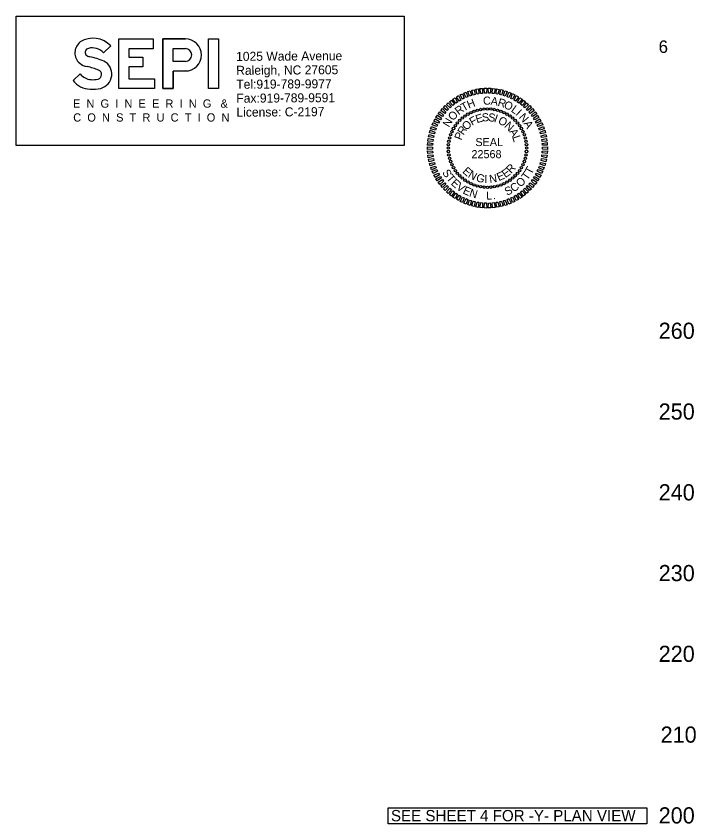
# Model space of a CAD drawing. Extents: x 2319808 to 2329388, y 152694 to 160631.
# Drawn here: x 2320852 to 2321272, y 152694 to 153194 of the extents above; entities that cross this region are included whole.
import ezdxf

# ---------------------------------------------------------------- set-up
doc = ezdxf.new("R2010")
doc.units = 0
for name, color, linetype in [('Exist Vertical Profile Vertical Axis Label', 7, 'Continuous'), ('Old_Level_2', 7, 'Continuous'), ('Old_Level_58', 7, 'Continuous'), ('Old_Level_61', 7, 'Continuous'), ('Prop Grid Mask', 7, 'Continuous'), ('Prop PFL Text', 7, 'Continuous'), ('Sheet Data Field CELL', 7, 'Continuous'), ('Sheet PE Seal Cell', 7, 'Continuous')]:
    doc.layers.add(name, color=color, linetype=linetype)

msp = doc.modelspace()

# ---------------------------------------------------------------- linework, layer by layer
at = {"layer": 'Old_Level_58'}
msp.add_lwpolyline([(2320852, 153193.7), (2321092.06, 153193.7), (2321092.06, 153113.67), (2320852, 153113.67)], close=True, dxfattribs=at)
at = {"layer": 'Old_Level_61'}
for p, q in [((2320910.53, 153175.25), (2320906.11, 153170.94)), ((2320915.52, 153179.56), (2320936.8, 153179.57)), ((2320915.52, 153148.91), (2320915.52, 153179.56)), ((2320936.8, 153179.57), (2320936.8, 153173.57)), ((2320956.69, 153179.57), (2320942.84, 153179.57)), ((2320970.97, 153179.57), (2320977.11, 153179.57)), ((2320970.97, 153148.91), (2320970.97, 153179.57)), ((2320977.11, 153179.57), (2320977.11, 153148.91)), ((2320936.8, 153173.57), (2320921.63, 153173.57)), ((2320921.63, 153173.57), (2320921.63, 153168.28)), ((2320921.63, 153168.28), (2320930.4, 153168.28)), ((2320930.4, 153168.28), (2320930.4, 153162.32)), ((2320956.69, 153165.72), (2320949.09, 153165.72)), ((2320930.4, 153162.32), (2320921.63, 153162.32)), ((2320921.63, 153162.32), (2320921.63, 153154.88)), ((2320887.18, 153153.96), (2320891.63, 153157.93)), ((2320921.63, 153154.88), (2320937.5, 153154.88)), ((2320937.5, 153154.88), (2320937.5, 153148.91)), ((2320937.5, 153148.91), (2320915.52, 153148.91)), ((2320977.11, 153148.91), (2320970.97, 153148.91))]:
    msp.add_line(p, q, dxfattribs=at)
for points in [[(2320942.84, 153179.57), (2320956.69, 153179.57)], [(2320956.69, 153159.75), (2320949.1, 153159.74), (2320949.1, 153148.91), (2320942.84, 153148.91), (2320942.84, 153179.57)], [(2320942.84, 153179.57), (2320942.84, 153148.91), (2320949.1, 153148.91), (2320949.1, 153159.74), (2320956.69, 153159.75)], [(2320949.09, 153165.72), (2320949.09, 153173.62), (2320956.69, 153173.62)], [(2320949.09, 153165.72), (2320949.09, 153173.62), (2320956.69, 153173.62)], [(2320956.69, 153165.72), (2320949.09, 153165.72)]]:
    msp.add_lwpolyline(points, dxfattribs=at)
for centre, radius, start, end in [((2320899.64, 153165.4), 14.68, 42.1327, 122.9781), ((2320896.85, 153170.99), 8.51, 127.737, 229.6653), ((2320956.69, 153169.66), 9.91, 270.0085, 90.0085), ((2320956.69, 153169.66), 9.91, 270.0085, 90.0085), ((2320897.26, 153171.29), 2.54, 103.531, 215.5148), ((2320899.12, 153164.73), 9.35, 41.6206, 105.1978), ((2320956.69, 153169.67), 3.95, 270.0085, 90.0085), ((2320956.69, 153169.67), 3.95, 270.0085, 90.0085), ((2320898.64, 153173.24), 4.86, 224.8336, 256.8488), ((2320889.71, 153126.77), 42.47, 67.2047, 79.3861), ((2320902.13, 153157.8), 9.06, 283.8987, 63.5916), ((2320898.66, 153174.58), 12.45, 234.0275, 257.3508), ((2320888.8, 153125.52), 37.6, 67.7856, 79.0604), ((2320901.85, 153157.62), 2.95, 286.1134, 66.6483), ((2320899.02, 153163.95), 9.54, 219.2143, 265.7729), ((2320897.99, 153161.91), 13.42, 216.3695, 269.0232), ((2320899.59, 153166.23), 11.85, 263.8472, 285.0485), ((2320899.48, 153168.72), 20.3, 265.1339, 283.7745)]:
    msp.add_arc(centre, radius, start, end, dxfattribs=at)
at = {"layer": 'Prop Grid Mask'}
msp.add_lwpolyline([(2321082.06, 152703.7), (2321242.06, 152703.7), (2321242.06, 152693.7), (2321082.06, 152693.7)], close=True, dxfattribs=at)
at = {"layer": 'Sheet PE Seal Cell'}
for points in [[(2321128.15, 153142.32), (2321126.58, 153145.01), (2321128.04, 153145.69), (2321129.18, 153142.83)], [(2321130.31, 153143.32), (2321128.92, 153146.12), (2321130.43, 153146.69), (2321131.36, 153143.75)], [(2321132.52, 153144.17), (2321131.33, 153147.05), (2321132.88, 153147.53), (2321133.61, 153144.53)], [(2321134.79, 153144.86), (2321133.81, 153147.82), (2321135.38, 153148.19), (2321135.9, 153145.14)], [(2321137.1, 153145.39), (2321136.33, 153148.42), (2321137.93, 153148.67), (2321138.23, 153145.6)], [(2321139.45, 153145.76), (2321138.89, 153148.83), (2321140.5, 153148.97), (2321140.58, 153145.89)], [(2321141.81, 153145.97), (2321141.46, 153149.07), (2321143.08, 153149.1), (2321142.95, 153146.01)], [(2321144.18, 153146.01), (2321144.05, 153149.13), (2321145.67, 153149.04), (2321145.32, 153145.97)], [(2321146.55, 153145.88), (2321146.64, 153149), (2321148.24, 153148.8), (2321147.69, 153145.77)], [(2321148.91, 153145.59), (2321149.21, 153148.7), (2321150.8, 153148.39), (2321150.03, 153145.4)], [(2321151.23, 153145.14), (2321151.76, 153148.21), (2321153.32, 153147.79), (2321152.34, 153144.87)], [(2321153.53, 153144.52), (2321154.26, 153147.55), (2321155.79, 153147.03), (2321154.61, 153144.17)], [(2321155.77, 153143.75), (2321156.71, 153146.72), (2321158.2, 153146.09), (2321156.83, 153143.33)], [(2321157.95, 153142.82), (2321159.1, 153145.72), (2321160.54, 153144.98), (2321158.98, 153142.32)], [(2321120.4, 153136.9), (2321118.14, 153139.05), (2321119.36, 153140.11), (2321121.24, 153137.67)], [(2321122.19, 153138.45), (2321120.09, 153140.76), (2321121.38, 153141.73), (2321123.09, 153139.16)], [(2321124.09, 153139.88), (2321122.15, 153142.33), (2321123.51, 153143.21), (2321125.03, 153140.52)], [(2321126.08, 153141.17), (2321124.32, 153143.75), (2321125.73, 153144.53), (2321127.06, 153141.75)], [(2321160.06, 153141.74), (2321161.42, 153144.55), (2321162.8, 153143.72), (2321161.06, 153141.17)], [(2321162.1, 153140.52), (2321163.64, 153143.23), (2321164.96, 153142.3), (2321163.05, 153139.88)], [(2321164.04, 153139.15), (2321165.77, 153141.75), (2321167.02, 153140.73), (2321164.94, 153138.46)], [(2321165.88, 153137.66), (2321167.79, 153140.13), (2321168.97, 153139.03), (2321166.74, 153136.9)], [(2321117.16, 153133.43), (2321114.63, 153135.25), (2321115.69, 153136.47), (2321117.89, 153134.31)], [(2321118.72, 153135.22), (2321116.32, 153137.21), (2321117.46, 153138.35), (2321119.51, 153136.05)], [(2321167.62, 153136.04), (2321169.69, 153138.37), (2321170.79, 153137.19), (2321168.42, 153135.22)], [(2321169.23, 153134.3), (2321171.47, 153136.49), (2321172.48, 153135.23), (2321169.97, 153133.43)], [(2321113.29, 153127.47), (2321110.43, 153128.73), (2321111.22, 153130.14), (2321113.82, 153128.49)], [(2321114.44, 153129.55), (2321111.68, 153131), (2321112.56, 153132.35), (2321115.04, 153130.52)], [(2321115.73, 153131.54), (2321113.08, 153133.17), (2321114.05, 153134.47), (2321116.4, 153132.47)], [(2321170.73, 153132.46), (2321173.1, 153134.48), (2321174.03, 153133.16), (2321171.4, 153131.54)], [(2321172.08, 153130.52), (2321174.6, 153132.37), (2321175.43, 153130.98), (2321172.7, 153129.55)], [(2321173.31, 153128.48), (2321175.94, 153130.15), (2321176.67, 153128.71), (2321173.85, 153127.48)], [(2321111.43, 153123.11), (2321108.43, 153123.95), (2321109.01, 153125.46), (2321111.82, 153124.19)], [(2321112.29, 153125.32), (2321109.35, 153126.37), (2321110.03, 153127.84), (2321112.74, 153126.37)], [(2321174.38, 153126.37), (2321177.13, 153127.85), (2321177.76, 153126.36), (2321174.85, 153125.33)], [(2321175.31, 153124.18), (2321178.15, 153125.47), (2321178.68, 153123.94), (2321175.7, 153123.11)], [(2321110.2, 153118.53), (2321107.11, 153118.95), (2321107.47, 153120.52), (2321110.43, 153119.65)], [(2321110.74, 153120.84), (2321107.68, 153121.47), (2321108.16, 153123.02), (2321111.05, 153121.94)], [(2321176.08, 153121.94), (2321179, 153123.02), (2321179.42, 153121.46), (2321176.4, 153120.84)], [(2321176.69, 153119.65), (2321179.68, 153120.52), (2321179.99, 153118.94), (2321176.93, 153118.53)], [(2321109.62, 153113.82), (2321106.5, 153113.81), (2321106.64, 153115.42), (2321109.69, 153114.96)], [(2321109.83, 153116.19), (2321106.72, 153116.39), (2321106.97, 153117.98), (2321109.98, 153117.32)], [(2321177.14, 153117.32), (2321180.19, 153117.98), (2321180.39, 153116.38), (2321177.31, 153116.19)], [(2321177.43, 153114.96), (2321180.52, 153115.41), (2321180.6, 153113.8), (2321177.52, 153113.82)], [(2321109.58, 153111.45), (2321106.47, 153111.22), (2321106.5, 153112.83), (2321109.57, 153112.59)], [(2321109.7, 153109.08), (2321106.61, 153108.63), (2321106.53, 153110.24), (2321109.61, 153110.22)], [(2321177.51, 153110.22), (2321180.63, 153110.24), (2321180.49, 153108.63), (2321177.44, 153109.08)], [(2321177.55, 153112.59), (2321180.66, 153112.83), (2321180.63, 153111.21), (2321177.56, 153111.45)], [(2321109.99, 153106.73), (2321106.94, 153106.06), (2321106.74, 153107.66), (2321109.82, 153107.86)], [(2321110.44, 153104.4), (2321107.45, 153103.52), (2321107.14, 153105.11), (2321110.2, 153105.51)], [(2321176.93, 153105.51), (2321180.02, 153105.1), (2321179.66, 153103.52), (2321176.7, 153104.39)], [(2321177.3, 153107.86), (2321180.41, 153107.66), (2321180.16, 153106.06), (2321177.15, 153106.72)], [(2321111.05, 153102.11), (2321108.13, 153101.02), (2321107.71, 153102.58), (2321110.73, 153103.2)], [(2321111.82, 153099.86), (2321108.98, 153098.58), (2321108.46, 153100.1), (2321111.43, 153100.93)], [(2321175.7, 153100.93), (2321178.7, 153100.09), (2321178.12, 153098.58), (2321175.31, 153099.86)], [(2321176.39, 153103.2), (2321179.45, 153102.57), (2321178.97, 153101.03), (2321176.08, 153102.1)], [(2321112.75, 153097.68), (2321110, 153096.2), (2321109.37, 153097.68), (2321112.28, 153098.72)], [(2321113.82, 153095.56), (2321111.19, 153093.89), (2321110.46, 153095.33), (2321113.28, 153096.57)], [(2321173.84, 153096.57), (2321176.7, 153095.32), (2321175.92, 153093.9), (2321173.31, 153095.56)], [(2321174.84, 153098.72), (2321177.78, 153097.67), (2321177.1, 153096.21), (2321174.39, 153097.67)], [(2321115.05, 153093.53), (2321112.53, 153091.68), (2321111.7, 153093.06), (2321114.43, 153094.49)], [(2321116.4, 153091.58), (2321114.03, 153089.56), (2321113.1, 153090.89), (2321115.73, 153092.5)], [(2321117.9, 153089.74), (2321115.67, 153087.56), (2321114.65, 153088.81), (2321117.16, 153090.61)], [(2321169.97, 153090.61), (2321172.5, 153088.79), (2321171.44, 153087.57), (2321169.24, 153089.73)], [(2321171.4, 153092.51), (2321174.05, 153090.87), (2321173.08, 153089.58), (2321170.73, 153091.58)], [(2321172.69, 153094.5), (2321175.45, 153093.05), (2321174.57, 153091.69), (2321172.09, 153093.52)], [(2321119.51, 153088), (2321117.44, 153085.67), (2321116.34, 153086.85), (2321118.71, 153088.82)], [(2321121.25, 153086.38), (2321119.34, 153083.91), (2321118.16, 153085.02), (2321120.39, 153087.14)], [(2321123.09, 153084.89), (2321121.36, 153082.29), (2321120.11, 153083.31), (2321122.19, 153085.59)], [(2321164.94, 153085.59), (2321167.04, 153083.29), (2321165.75, 153082.31), (2321164.04, 153084.88)], [(2321166.73, 153087.15), (2321168.99, 153084.99), (2321167.77, 153083.93), (2321165.89, 153086.38)], [(2321168.41, 153088.82), (2321170.81, 153086.83), (2321169.67, 153085.69), (2321167.62, 153088)], [(2321125.03, 153083.53), (2321123.49, 153080.82), (2321122.17, 153081.74), (2321124.08, 153084.16)], [(2321127.07, 153082.3), (2321125.71, 153079.49), (2321124.33, 153080.32), (2321126.07, 153082.87)], [(2321129.18, 153081.23), (2321128.03, 153078.33), (2321126.59, 153079.06), (2321128.15, 153081.72)], [(2321131.36, 153080.3), (2321130.42, 153077.32), (2321128.93, 153077.96), (2321130.3, 153080.72)], [(2321156.82, 153080.72), (2321158.21, 153077.93), (2321156.7, 153077.35), (2321155.77, 153080.29)], [(2321158.98, 153081.73), (2321160.55, 153079.03), (2321159.09, 153078.35), (2321157.95, 153081.22)], [(2321161.05, 153082.87), (2321162.81, 153080.3), (2321161.4, 153079.51), (2321160.07, 153082.3)], [(2321163.04, 153084.17), (2321164.98, 153081.72), (2321163.62, 153080.84), (2321162.1, 153083.52)], [(2321133.61, 153079.52), (2321132.87, 153076.49), (2321131.34, 153077.02), (2321132.52, 153079.87)], [(2321135.9, 153078.91), (2321135.37, 153075.83), (2321133.81, 153076.25), (2321134.79, 153079.18)], [(2321138.22, 153078.45), (2321137.92, 153075.35), (2321136.33, 153075.66), (2321137.1, 153078.64)], [(2321140.58, 153078.16), (2321140.49, 153075.04), (2321138.89, 153075.24), (2321139.44, 153078.27)], [(2321142.95, 153078.04), (2321143.08, 153074.92), (2321141.46, 153075), (2321141.81, 153078.07)], [(2321145.32, 153078.08), (2321145.67, 153074.98), (2321144.05, 153074.95), (2321144.18, 153078.03)], [(2321147.68, 153078.28), (2321148.25, 153075.21), (2321146.64, 153075.07), (2321146.55, 153078.16)], [(2321150.03, 153078.65), (2321150.8, 153075.63), (2321149.21, 153075.38), (2321148.9, 153078.45)], [(2321152.34, 153079.18), (2321153.32, 153076.22), (2321151.75, 153075.86), (2321151.23, 153078.9)], [(2321154.61, 153079.88), (2321155.8, 153076.99), (2321154.25, 153076.52), (2321153.53, 153079.52)]]:
    msp.add_lwpolyline(points, close=True, dxfattribs=at)
for centre in [(2321135.27, 153134.81), (2321137.29, 153135.45), (2321139.35, 153135.9), (2321141.45, 153136.18), (2321143.57, 153136.27), (2321145.68, 153136.18), (2321147.78, 153135.9), (2321149.84, 153135.45), (2321151.86, 153134.81), (2321127.98, 153130.6), (2321129.66, 153131.89), (2321131.44, 153133.02), (2321133.32, 153134), (2321153.81, 153134), (2321155.69, 153133.02), (2321157.47, 153131.89), (2321159.15, 153130.6), (2321123.7, 153125.93), (2321124.99, 153127.61), (2321126.42, 153129.17), (2321160.71, 153129.17), (2321162.14, 153127.61), (2321163.43, 153125.93), (2321120.78, 153120.32), (2321121.59, 153122.27), (2321122.56, 153124.15), (2321164.57, 153124.15), (2321165.54, 153122.27), (2321166.35, 153120.32), (2321119.68, 153116.23), (2321120.14, 153118.3), (2321166.99, 153118.3), (2321167.45, 153116.23), (2321119.32, 153112.02), (2321119.41, 153114.14), (2321119.41, 153109.91), (2321167.72, 153114.14), (2321167.72, 153109.91), (2321167.82, 153112.02), (2321119.68, 153107.81), (2321120.14, 153105.75), (2321166.99, 153105.75), (2321167.45, 153107.81), (2321120.78, 153103.73), (2321121.59, 153101.77), (2321122.56, 153099.9), (2321164.57, 153099.9), (2321165.54, 153101.77), (2321166.35, 153103.73), (2321123.7, 153098.11), (2321124.99, 153096.43), (2321126.42, 153094.87), (2321160.71, 153094.87), (2321162.14, 153096.43), (2321163.43, 153098.11), (2321127.98, 153093.45), (2321129.66, 153092.16), (2321131.44, 153091.02), (2321133.32, 153090.04), (2321153.81, 153090.04), (2321155.69, 153091.02), (2321157.47, 153092.16), (2321159.15, 153093.45), (2321135.27, 153089.23), (2321137.29, 153088.6), (2321139.35, 153088.14), (2321141.45, 153087.86), (2321143.57, 153087.77), (2321145.68, 153087.86), (2321147.78, 153088.14), (2321149.84, 153088.6), (2321151.86, 153089.23)]:
    msp.add_circle(centre, 0.75, dxfattribs=at)

# ---------------------------------------------------------------- texts
at = {"layer": 'Exist Vertical Profile Vertical Axis Label'}
for s, p in [('260', (2321249.49, 152993.95)), ('250', (2321249.49, 152943.95)), ('240', (2321249.49, 152893.95)), ('230', (2321249.49, 152843.95)), ('220', (2321249.49, 152793.95)), ('210', (2321250.69, 152743.95)), ('200', (2321249.49, 152693.95))]:
    msp.add_text(s, height=10, dxfattribs=at).set_placement(p)
at = {"layer": 'Old_Level_2'}
for s, height, rotation, p in [('1025 Wade Avenue', 5.5891, 0.348, (2320988.08, 153165.99)), ('Raleigh, NC 27605', 5.5891, 0.348, (2320988.13, 153157.36)), ('Tel:919-789-9977 ', 5.5891, 0.348, (2320988.19, 153148.72)), ('Fax:919-789-9591', 5.5891, 0.348, (2320988.24, 153140.09)), ('E  N  G  I  N  E  E  R  I  N  G   &', 5.1, 0.0086, (2320887.13, 153137.04)), ('License: C-2197', 5.5891, 0.348, (2320988.29, 153131.45)), ('C  O  N  S  T  R  U  C  T  I  O  N', 5.1, 0.0086, (2320887.3, 153128.43))]:
    msp.add_text(s, height=height, rotation=rotation, dxfattribs=at).set_placement(p)
at = {"layer": 'Prop PFL Text'}
msp.add_text('SEE SHEET 4 FOR -Y- PLAN VIEW', height=7, dxfattribs=at).set_placement((2321083.85, 152695.28))
at = {"layer": 'Sheet Data Field CELL'}
msp.add_text('6', height=7.75, dxfattribs=at).set_placement((2321249.47, 153170.95))
at = {"layer": 'Sheet PE Seal Cell'}
for s, rotation, p in [('T', 29.3903, (2321128.85, 153134.58)), ('H', 21.601, (2321132.04, 153136.37)), ('C', 1.9618, (2321140.9, 153138.82)), ('A', 352.4568, (2321145.36, 153138.89)), ('R', 343.4093, (2321149.56, 153138.28)), ('O', 335.2006, (2321153.25, 153137.15)), ('R', 37.5989, (2321125.78, 153132.25)), ('L', 324.4755, (2321157.76, 153134.91)), ('I', 317.0103, (2321160.61, 153132.87)), ('N', 58.5345, (2321119.73, 153124.56)), ('O', 48.3241, (2321122.33, 153128.58)), ('F', 28.6639, (2321134.06, 153125.77)), ('E', 16.986, (2321137.03, 153127.41)), ('S', 5.2237, (2321140.31, 153128.42)), ('S', 353.2648, (2321143.78, 153128.74)), ('I', 341.3058, (2321147.24, 153128.33)), ('O', 332.5504, (2321149.68, 153127.58)), ('N', 311.0704, (2321162.68, 153131)), ('R', 56.5721, (2321128.73, 153119.72)), ('O', 44.4727, (2321130.67, 153122.66)), ('N', 316.7416, (2321153.68, 153125.33)), ('A', 300.8599, (2321165.74, 153127.31)), ('P', 68.3344, (2321127.47, 153116.53)), ('A', 301.6915, (2321156.79, 153122.24)), ('L', 288.3556, (2321158.79, 153118.92)), ('E', 317.8506, (2321127.76, 153097.16)), ('R', 47.043, (2321158.2, 153096)), ('T', 62.3829, (2321170.76, 153095.25)), ('S', 302.1713, (2321115.38, 153096.96)), ('T', 310.2847, (2321117.79, 153093.13)), ('N', 329.6129, (2321131.12, 153094.25)), ('G', 344.6629, (2321136.16, 153091.63)), ('I', 359.713, (2321141.71, 153090.41)), ('N', 8.4684, (2321145.02, 153090.38)), ('E', 23.5185, (2321150.59, 153091.5)), ('E', 35.2807, (2321154.63, 153093.36)), ('T', 54.5936, (2321168.24, 153091.72)), ('E', 318.0739, (2321120.59, 153089.81)), ('V', 326.0538, (2321123.89, 153086.84)), ('C', 34.3634, (2321159.69, 153084.44)), ('O', 43.8685, (2321164.03, 153087.48)), ('E', 334.739, (2321127.92, 153084.16)), ('N', 342.7189, (2321131.94, 153082.26)), ('L', 2.8157, (2321142.88, 153080.07)), ('S', 26.2501, (2321155.64, 153082.44)), ('.', 10.2808, (2321147.03, 153080.26))]:
    msp.add_text(s, height=5, rotation=rotation, dxfattribs=at).set_placement(p)
for s, p in [('SEAL', (2321136.09, 153113.27)), ('22568', (2321133.68, 153105.77))]:
    msp.add_text(s, height=5, dxfattribs=at).set_placement(p)

doc.saveas('drawing.dxf')
